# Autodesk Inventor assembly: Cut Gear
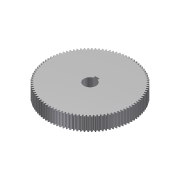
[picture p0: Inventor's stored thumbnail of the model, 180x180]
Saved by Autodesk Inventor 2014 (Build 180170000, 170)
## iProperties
Created: 2011-01
Part Number: Cut Gear
Document SubType Name: Assembly
Designer: Beta-8540w
Categories: <?xml version="1.0" encoding="UTF-16"?> <MemberInstance><Categories><FamilyTemplate/><ParamToTemplateMap><ParamToTemplate><ParamToTemplate CategoryParameter="//
ClientObjectVersion: 1
Author: Beta-8540w
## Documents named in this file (2)
- C:\Inventor 2014 Essentials\Assemblies\Chapter 09\Design Accelerators\Spur Gear c09-01.iam
- C:\Inventor 2014 Essentials\Assemblies\Chapter 09\Design Accelerators\Spur Gear c09-01.ipt
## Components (1 placed, 1 different names)
1. Spur Gear:1
